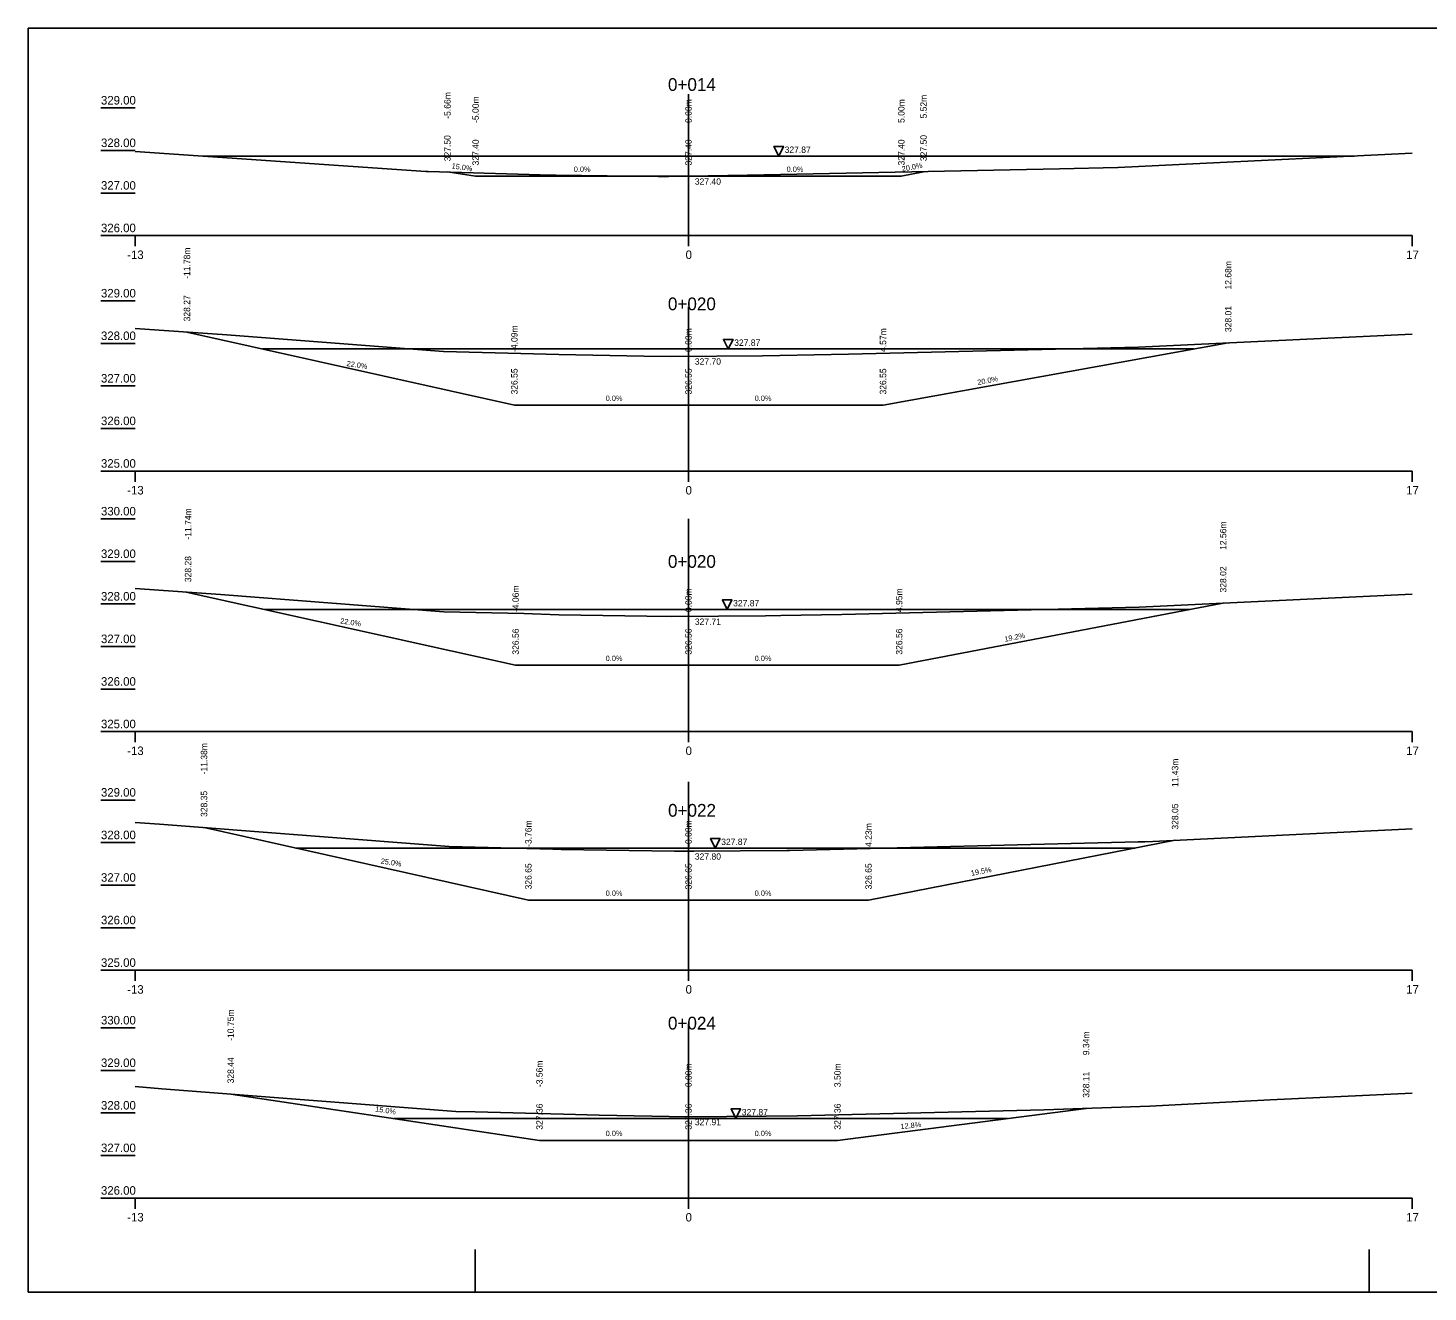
# Model space of a CAD drawing. Extents: x -557810.4 to -557757.9, y -1162710 to -1162680.3.
# Drawn here: x -557810.37 to -557777.49, y -1162709.97 to -1162680.27 of the extents above; entities that cross this region are included whole.
import ezdxf

# ---------------------------------------------------------------- set-up
doc = ezdxf.new("R2010")
doc.units = 0
for name, color, linetype in [('16', 7, 'Continuous'), ('21', 7, 'Continuous'), ('28', 7, 'Continuous'), ('59', 7, 'Continuous'), ('Body pricny rez', 7, 'Continuous'), ('Popis pricneho profilu', 7, 'Continuous')]:
    doc.layers.add(name, color=color, linetype=linetype)

msp = doc.modelspace()

# ---------------------------------------------------------------- linework, layer by layer
for p, q in [((-557757.872, -1162680.266), (-557810.372, -1162680.266)), ((-557810.372, -1162680.266), (-557810.372, -1162709.966)), ((-557799.872, -1162709.966), (-557799.872, -1162708.966)), ((-557778.872, -1162709.966), (-557778.872, -1162708.966)), ((-557810.372, -1162709.966), (-557757.872, -1162709.966))]:
    msp.add_line(p, q)
for points in [[(-557792.739, -1162683.274), (-557792.851, -1162683.049), (-557792.626, -1162683.049)], [(-557793.923, -1162687.807), (-557794.036, -1162687.582), (-557793.811, -1162687.582)], [(-557793.948, -1162693.929), (-557794.061, -1162693.704), (-557793.836, -1162693.704)], [(-557794.228, -1162699.536), (-557794.34, -1162699.311), (-557794.115, -1162699.311)], [(-557793.745, -1162705.889), (-557793.857, -1162705.664), (-557793.632, -1162705.664)]]:
    msp.add_lwpolyline(points, close=True)
for points in [[(-557807.858, -1162683.164), (-557801.026, -1162683.634), (-557800.973, -1162683.634), (-557798.076, -1162683.725), (-557797.999, -1162683.726), (-557797.966, -1162683.727), (-557795.567, -1162683.756), (-557795.33, -1162683.755), (-557793.475, -1162683.727), (-557786.141, -1162683.578), (-557784.776, -1162683.545), (-557784.767, -1162683.545), (-557783.335, -1162683.477), (-557777.858, -1162683.207)], [(-557806.256, -1162683.274), (-557779.221, -1162683.274)], [(-557800.52, -1162683.648), (-557799.858, -1162683.747), (-557794.858, -1162683.747), (-557789.858, -1162683.747), (-557789.336, -1162683.643)], [(-557799.858, -1162683.747), (-557800.52, -1162683.648)], [(-557799.858, -1162683.747), (-557800.52, -1162683.648)], [(-557794.858, -1162683.747), (-557799.858, -1162683.747)], [(-557794.858, -1162683.747), (-557799.858, -1162683.747)], [(-557794.858, -1162683.747), (-557789.858, -1162683.747)], [(-557794.858, -1162683.747), (-557789.858, -1162683.747)], [(-557789.858, -1162683.747), (-557789.336, -1162683.643)], [(-557789.858, -1162683.747), (-557789.336, -1162683.643)], [(-557807.858, -1162687.327), (-557805.698, -1162687.475), (-557800.614, -1162687.869), (-557798.797, -1162687.913), (-557797.907, -1162687.941), (-557795.908, -1162687.974), (-557795.269, -1162687.981), (-557793.118, -1162687.967), (-557792.71, -1162687.961), (-557791.099, -1162687.928), (-557784.289, -1162687.762), (-557784.287, -1162687.762), (-557777.858, -1162687.456)], [(-557794.858, -1162689.128), (-557798.948, -1162689.128), (-557806.638, -1162687.41)], [(-557790.288, -1162689.128), (-557782.178, -1162687.661)], [(-557804.863, -1162687.807), (-557782.983, -1162687.807)], [(-557794.858, -1162689.128), (-557798.358, -1162689.128)], [(-557794.858, -1162689.128), (-557791.358, -1162689.128)], [(-557794.858, -1162689.128), (-557790.288, -1162689.128)], [(-557807.858, -1162693.437), (-557805.849, -1162693.575), (-557800.601, -1162693.982), (-557798.726, -1162694.027), (-557797.901, -1162694.053), (-557795.839, -1162694.086), (-557795.26, -1162694.093), (-557793.048, -1162694.079), (-557792.686, -1162694.073), (-557791.255, -1162694.044), (-557784.273, -1162693.873), (-557784.272, -1162693.873), (-557777.858, -1162693.569)], [(-557794.858, -1162695.24), (-557798.918, -1162695.24), (-557806.655, -1162693.519)], [(-557804.815, -1162693.929), (-557783.081, -1162693.929)], [(-557789.908, -1162695.24), (-557782.308, -1162693.78)], [(-557794.858, -1162695.24), (-557798.358, -1162695.24)], [(-557794.858, -1162695.24), (-557791.358, -1162695.24)], [(-557794.858, -1162695.24), (-557789.908, -1162695.24)], [(-557807.858, -1162698.934), (-557807.285, -1162698.973), (-557800.479, -1162699.501), (-557798.047, -1162699.559), (-557797.85, -1162699.566), (-557795.189, -1162699.609), (-557795.171, -1162699.609), (-557794.732, -1162699.606), (-557792.548, -1162699.594), (-557792.476, -1162699.593), (-557784.296, -1162699.392), (-557784.135, -1162699.386), (-557783.952, -1162699.377), (-557777.858, -1162699.082)], [(-557794.858, -1162700.757), (-557798.618, -1162700.757), (-557806.238, -1162699.054)], [(-557804.083, -1162699.536), (-557784.373, -1162699.536)], [(-557790.628, -1162700.757), (-557783.428, -1162699.351)], [(-557794.858, -1162700.757), (-557798.358, -1162700.757)], [(-557794.858, -1162700.757), (-557791.358, -1162700.757)], [(-557794.858, -1162700.757), (-557790.628, -1162700.757)], [(-557807.858, -1162705.134), (-557807.228, -1162705.189), (-557800.319, -1162705.725), (-557799.87, -1162705.736), (-557797.796, -1162705.786), (-557797.793, -1162705.786), (-557796.957, -1162705.812), (-557794.897, -1162705.848), (-557793.032, -1162705.838), (-557792.299, -1162705.828), (-557786.504, -1162705.685), (-557784.02, -1162705.602), (-557781.192, -1162705.454), (-557777.858, -1162705.293)], [(-557798.358, -1162706.402), (-557805.611, -1162705.314)], [(-557798.358, -1162706.402), (-557805.611, -1162705.314)], [(-557791.358, -1162706.402), (-557785.518, -1162705.652)], [(-557801.779, -1162705.889), (-557787.364, -1162705.889)], [(-557794.858, -1162706.402), (-557798.358, -1162706.402)], [(-557794.858, -1162706.402), (-557798.358, -1162706.402)], [(-557794.858, -1162706.402), (-557791.358, -1162706.402)], [(-557794.858, -1162706.402), (-557791.358, -1162706.402)]]:
    msp.add_lwpolyline(points)
at = {"layer": '16'}
for p, q in [((-557807.858, -1162685.144), (-557777.858, -1162685.144)), ((-557807.858, -1162690.677), (-557777.858, -1162690.677)), ((-557807.858, -1162696.799), (-557777.858, -1162696.799)), ((-557807.858, -1162702.406), (-557777.858, -1162702.406)), ((-557807.858, -1162707.759), (-557777.858, -1162707.759))]:
    msp.add_line(p, q, dxfattribs=at)
at = {"layer": '21'}
for p, q in [((-557808.658, -1162682.144), (-557807.858, -1162682.144)), ((-557808.658, -1162683.144), (-557807.858, -1162683.144)), ((-557808.658, -1162684.144), (-557807.858, -1162684.144)), ((-557808.658, -1162685.144), (-557807.858, -1162685.144)), ((-557808.658, -1162686.677), (-557807.858, -1162686.677)), ((-557808.658, -1162687.677), (-557807.858, -1162687.677)), ((-557808.658, -1162688.677), (-557807.858, -1162688.677)), ((-557808.658, -1162689.677), (-557807.858, -1162689.677)), ((-557808.658, -1162690.677), (-557807.858, -1162690.677)), ((-557808.658, -1162691.799), (-557807.858, -1162691.799)), ((-557808.658, -1162692.799), (-557807.858, -1162692.799)), ((-557808.658, -1162693.799), (-557807.858, -1162693.799)), ((-557808.658, -1162694.799), (-557807.858, -1162694.799)), ((-557808.658, -1162695.799), (-557807.858, -1162695.799)), ((-557808.658, -1162696.799), (-557807.858, -1162696.799)), ((-557808.658, -1162698.406), (-557807.858, -1162698.406)), ((-557808.658, -1162699.406), (-557807.858, -1162699.406)), ((-557808.658, -1162700.406), (-557807.858, -1162700.406)), ((-557808.658, -1162701.406), (-557807.858, -1162701.406)), ((-557808.658, -1162702.406), (-557807.858, -1162702.406)), ((-557808.658, -1162703.759), (-557807.858, -1162703.759)), ((-557808.658, -1162704.759), (-557807.858, -1162704.759)), ((-557808.658, -1162705.759), (-557807.858, -1162705.759)), ((-557808.658, -1162706.759), (-557807.858, -1162706.759)), ((-557808.658, -1162707.759), (-557807.858, -1162707.759))]:
    msp.add_line(p, q, dxfattribs=at)
at = {"layer": '28'}
for p, q in [((-557794.858, -1162681.82), (-557794.858, -1162685.144)), ((-557794.858, -1162686.818), (-557794.858, -1162690.677)), ((-557794.858, -1162691.799), (-557794.858, -1162696.799)), ((-557794.858, -1162697.982), (-557794.858, -1162702.406)), ((-557794.858, -1162703.666), (-557794.858, -1162707.759))]:
    msp.add_line(p, q, dxfattribs=at)
at = {"layer": '59'}
for p, q in [((-557807.858, -1162685.394), (-557807.858, -1162685.144)), ((-557794.858, -1162685.394), (-557794.858, -1162685.144)), ((-557777.858, -1162685.394), (-557777.858, -1162685.144)), ((-557807.858, -1162690.927), (-557807.858, -1162690.677)), ((-557794.858, -1162690.927), (-557794.858, -1162690.677)), ((-557777.858, -1162690.927), (-557777.858, -1162690.677)), ((-557807.858, -1162697.049), (-557807.858, -1162696.799)), ((-557794.858, -1162697.049), (-557794.858, -1162696.799)), ((-557777.858, -1162697.049), (-557777.858, -1162696.799)), ((-557807.858, -1162702.656), (-557807.858, -1162702.406)), ((-557794.858, -1162702.656), (-557794.858, -1162702.406)), ((-557777.858, -1162702.656), (-557777.858, -1162702.406)), ((-557807.858, -1162708.009), (-557807.858, -1162707.759)), ((-557794.858, -1162708.009), (-557794.858, -1162707.759)), ((-557777.858, -1162708.009), (-557777.858, -1162707.759))]:
    msp.add_line(p, q, dxfattribs=at)

# ---------------------------------------------------------------- texts
for s, height, p in [('0+014', 0.3, (-557795.34, -1162681.744)), ('327.87', 0.15, (-557792.599, -1162683.201)), ('0+020', 0.3, (-557795.341, -1162686.898)), ('327.87', 0.15, (-557793.784, -1162687.734)), ('0+020', 0.3, (-557795.341, -1162692.95)), ('327.87', 0.15, (-557793.809, -1162693.856)), ('0+022', 0.3, (-557795.338, -1162698.798)), ('327.87', 0.15, (-557794.089, -1162699.463)), ('0+024', 0.3, (-557795.34, -1162703.798)), ('327.87', 0.15, (-557793.605, -1162705.816))]:
    msp.add_text(s, height=height).set_placement(p)
for s, rotation, p in [('19.2%', 11.3099, (-557787.423, -1162694.689)), ('19.5%', 11.3099, (-557788.211, -1162700.19)), ('12.8%', 6.1255, (-557789.871, -1162706.14))]:
    msp.add_text(s, height=0.125, rotation=rotation).set_placement(p)
at = {"layer": '16'}
for s, rotation, p in [('15.0%', 351.4692, (-557800.428, -1162683.562)), ('20.0%', 11.3099, (-557789.834, -1162683.643)), ('22.0%', 351.4692, (-557802.895, -1162688.208)), ('20.0%', 11.3099, (-557788.059, -1162688.659)), ('22.0%', 351.4692, (-557803.044, -1162694.255)), ('25.0%', 351.4692, (-557802.094, -1162699.898)), ('15.0%', 351.4692, (-557802.224, -1162705.722))]:
    msp.add_text(s, height=0.125, rotation=rotation, dxfattribs=at).set_placement(p)
for p in [(-557797.552, -1162683.647), (-557792.552, -1162683.647), (-557796.802, -1162689.028), (-557793.302, -1162689.028), (-557796.802, -1162695.14), (-557793.302, -1162695.14), (-557796.802, -1162700.657), (-557793.302, -1162700.657), (-557796.802, -1162706.302), (-557793.302, -1162706.302)]:
    msp.add_text('0.0%', height=0.125, dxfattribs=at).set_placement(p)
at = {"layer": '21'}
for s, p in [('329.00', (-557808.658, -1162682.064)), ('328.00', (-557808.658, -1162683.064)), ('327.00', (-557808.658, -1162684.064)), ('326.00', (-557808.658, -1162685.064)), ('-13', (-557808.042, -1162685.694)), ('0', (-557794.925, -1162685.694)), ('17', (-557777.998, -1162685.694)), ('329.00', (-557808.658, -1162686.597)), ('328.00', (-557808.658, -1162687.597)), ('327.00', (-557808.658, -1162688.597)), ('326.00', (-557808.658, -1162689.597)), ('325.00', (-557808.658, -1162690.597)), ('-13', (-557808.042, -1162691.227)), ('0', (-557794.925, -1162691.227)), ('17', (-557777.998, -1162691.227)), ('330.00', (-557808.658, -1162691.719)), ('329.00', (-557808.658, -1162692.719)), ('328.00', (-557808.658, -1162693.719)), ('327.00', (-557808.658, -1162694.719)), ('326.00', (-557808.658, -1162695.719)), ('325.00', (-557808.658, -1162696.719)), ('-13', (-557808.042, -1162697.349)), ('0', (-557794.925, -1162697.349)), ('17', (-557777.998, -1162697.349)), ('329.00', (-557808.658, -1162698.326)), ('328.00', (-557808.658, -1162699.326)), ('327.00', (-557808.658, -1162700.326)), ('326.00', (-557808.658, -1162701.326)), ('325.00', (-557808.658, -1162702.326)), ('-13', (-557808.042, -1162702.956)), ('0', (-557794.925, -1162702.956)), ('17', (-557777.998, -1162702.956)), ('330.00', (-557808.658, -1162703.679)), ('329.00', (-557808.658, -1162704.679)), ('328.00', (-557808.658, -1162705.679)), ('327.00', (-557808.658, -1162706.679)), ('326.00', (-557808.658, -1162707.679)), ('-13', (-557808.042, -1162708.309)), ('0', (-557794.925, -1162708.309)), ('17', (-557777.998, -1162708.309))]:
    msp.add_text(s, height=0.2, dxfattribs=at).set_placement(p)
at = {"layer": '59'}
for s, p in [('327.40', (-557794.708, -1162683.947)), ('327.70', (-557794.708, -1162688.178)), ('327.71', (-557794.708, -1162694.291)), ('327.80', (-557794.708, -1162699.807)), ('327.91', (-557794.708, -1162706.048))]:
    msp.add_text(s, height=0.15, dxfattribs=at).set_placement(p)
at = {"layer": 'Body pricny rez'}
for p in [(-557807.618, -1162683.181), (-557807.618, -1162683.181), (-557801.387, -1162683.609), (-557801.387, -1162683.609), (-557800.52, -1162683.649), (-557800.52, -1162683.649), (-557799.858, -1162683.748), (-557799.858, -1162683.748), (-557798.035, -1162683.727), (-557798.035, -1162683.727), (-557794.858, -1162683.748), (-557794.858, -1162683.748), (-557789.858, -1162683.748), (-557789.858, -1162683.748), (-557789.336, -1162683.643), (-557789.336, -1162683.643), (-557784.56, -1162687.769), (-557784.56, -1162687.769), (-557798.358, -1162689.128), (-557798.358, -1162689.128), (-557794.858, -1162689.128), (-557794.858, -1162689.128), (-557791.358, -1162689.128), (-557791.358, -1162689.128), (-557784.561, -1162693.881), (-557784.561, -1162693.881), (-557798.358, -1162695.241), (-557798.358, -1162695.241), (-557794.858, -1162695.241), (-557794.858, -1162695.241), (-557791.358, -1162695.241), (-557791.358, -1162695.241), (-557784.564, -1162699.399), (-557784.564, -1162699.399), (-557798.358, -1162700.758), (-557798.358, -1162700.758), (-557794.858, -1162700.758), (-557794.858, -1162700.758), (-557791.358, -1162700.758), (-557791.358, -1162700.758), (-557805.612, -1162705.315), (-557805.612, -1162705.315), (-557787.95, -1162705.721), (-557787.95, -1162705.721), (-557798.358, -1162706.403), (-557798.358, -1162706.403), (-557794.858, -1162706.403), (-557794.858, -1162706.403), (-557791.358, -1162706.403), (-557791.358, -1162706.403)]:
    msp.add_text('+', height=0.001, dxfattribs=at).set_placement(p)
at = {"layer": 'Popis pricneho profilu'}
for s, p in [('-5.66m', (-557800.445, -1162682.398)), ('-5.00m', (-557799.783, -1162682.497)), ('0.00m', (-557794.783, -1162682.497)), ('5.00m', (-557789.783, -1162682.497)), ('5.52m', (-557789.261, -1162682.393)), ('327.50', (-557800.445, -1162683.398)), ('327.50', (-557789.261, -1162683.393)), ('327.40', (-557799.783, -1162683.497)), ('327.40', (-557794.783, -1162683.497)), ('327.40', (-557789.783, -1162683.497)), ('-11.78m', (-557806.563, -1162686.16)), ('12.68m', (-557782.103, -1162686.411)), ('328.27', (-557806.563, -1162687.16)), ('328.01', (-557782.103, -1162687.411)), ('-4.09m', (-557798.873, -1162687.878)), ('0.00m', (-557794.783, -1162687.878)), ('4.57m', (-557790.213, -1162687.878)), ('326.55', (-557798.873, -1162688.878)), ('326.55', (-557794.783, -1162688.878)), ('326.55', (-557790.213, -1162688.878)), ('-11.74m', (-557806.538, -1162692.287)), ('12.56m', (-557782.223, -1162692.53)), ('328.28', (-557806.538, -1162693.287)), ('328.02', (-557782.223, -1162693.53)), ('-4.06m', (-557798.843, -1162693.99)), ('0.00m', (-557794.783, -1162693.99)), ('4.95m', (-557789.833, -1162693.99)), ('326.56', (-557798.843, -1162694.99)), ('326.56', (-557794.783, -1162694.99)), ('326.56', (-557789.833, -1162694.99)), ('-11.38m', (-557806.163, -1162697.804)), ('11.43m', (-557783.353, -1162698.101)), ('328.35', (-557806.163, -1162698.804)), ('328.05', (-557783.353, -1162699.101)), ('-3.76m', (-557798.543, -1162699.507)), ('-0.00m', (-557794.783, -1162699.507)), ('4.23m', (-557790.553, -1162699.507)), ('326.65', (-557798.543, -1162700.507)), ('326.65', (-557794.783, -1162700.507)), ('326.65', (-557790.553, -1162700.507)), ('-10.75m', (-557805.536, -1162704.064)), ('9.34m', (-557785.443, -1162704.402)), ('328.44', (-557805.536, -1162705.064)), ('-3.56m', (-557798.283, -1162705.152)), ('0.00m', (-557794.783, -1162705.152)), ('3.50m', (-557791.283, -1162705.152)), ('328.11', (-557785.443, -1162705.402)), ('327.36', (-557798.283, -1162706.152)), ('327.36', (-557794.783, -1162706.152)), ('327.36', (-557791.283, -1162706.152))]:
    msp.add_text(s, height=0.15, rotation=90, dxfattribs=at).set_placement(p)

doc.saveas('drawing.dxf')
